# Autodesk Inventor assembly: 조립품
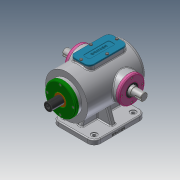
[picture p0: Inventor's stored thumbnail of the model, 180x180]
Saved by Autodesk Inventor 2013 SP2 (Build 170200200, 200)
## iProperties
Created: 2021-11
Part Number: 조립품
Document SubType Name: Assembly
Designer: i
Author: i
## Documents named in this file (14)
- C:\Users\i\Desktop\711106v1020\조립품.iam
- C:\Users\i\Desktop\711106v1020\본체.ipt
- C:\Users\i\Desktop\711106v1020\베어링 6205.ipt
- 베어링 6205.ipt
- C:\Users\i\Desktop\711106v1020\볼트 M4x0.7.ipt
- C:\Users\i\Desktop\711106v1020\부시.ipt
- C:\Users\i\Desktop\711106v1020\상부커버.ipt
- C:\Users\i\Desktop\711106v1020\슬라이드 커버.ipt
- C:\Users\i\Desktop\711106v1020\슬라이드.ipt
- C:\Users\i\Desktop\711106v1020\오일실.ipt
- 오일실.ipt
- C:\Users\i\Desktop\711106v1020\육각머리볼트 M4.ipt
- C:\Users\i\Desktop\711106v1020\축 커버.ipt
- C:\Users\i\Desktop\711106v1020\편심축.ipt
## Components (12 placed, 1 different names)
1. M4x0.7:2
2. M4x0.7:3
3. M4x0.7:4
4. M4x0.7:5
5. M4x0.7:1
6. M4x0.7:6
7. M4x0.7:7
8. M4x0.7:8
9. M4x0.7:9
10. M4x0.7:10
11. M4x0.7:11
12. M4x0.7:12
